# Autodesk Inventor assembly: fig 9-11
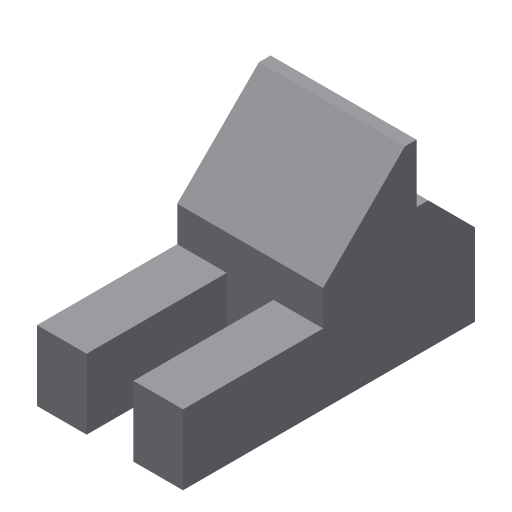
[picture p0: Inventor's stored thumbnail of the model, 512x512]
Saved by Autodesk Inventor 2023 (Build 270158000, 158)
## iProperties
Created: 2002-01
Part Number: fig 9-11
Document SubType Name: Assembly
Designer: ***
Control State: 0
Master: False
Checked Out: False
Shininess: 64.0
Length Units: 11269
Angle Units: 11279
Time Units: 11290
Mass Units: 11283
Length Display Precision: 3
Angle Display Precision: 2
Density: 0.0
Volumn: 0.0
Area: 0.0
PropertySet Name: Model Information
Author: ***
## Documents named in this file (3)
- D:\PROJECTS\Project 2022\Autodesk Inventor For Professional 2023\RESOURCES INVENTOR 2023\RESOURCES INVENTOR 2023\Inventor_2023_Part\Inventor_2023_Part\c09_Inv_2023_prt\fig 9-11.iam
- D:\PROJECTS\Project 2022\Autodesk Inventor For Professional 2023\RESOURCES INVENTOR 2023\RESOURCES INVENTOR 2023\Inventor_2023_Part\Inventor_2023_Part\c09_Inv_2023_prt\Part3.ipt
- D:\PROJECTS\Project 2022\Autodesk Inventor For Professional 2023\RESOURCES INVENTOR 2023\RESOURCES INVENTOR 2023\Inventor_2023_Part\Inventor_2023_Part\c09_Inv_2023_prt\Part4.ipt
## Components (2 placed, 2 different names)
1. Part3:1 — Mate:1
2. Part4:1 — Mate:1
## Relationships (1: Mate 1)
- Mate:1: Part3:1 ↔ Part4:1
